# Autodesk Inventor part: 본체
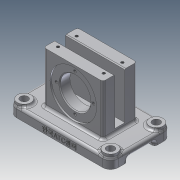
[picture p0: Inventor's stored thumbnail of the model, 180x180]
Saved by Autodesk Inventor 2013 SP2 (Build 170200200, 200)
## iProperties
Created: 2025-04
Part Number: 본체
Material: 알루미늄 6061
Document SubType Name: Modeling
Designer: i
Density: 2.71 g/cm^3
Mass: 495.705 g
Surface Area: 439.516 cm^2
Volume: 182.917 cm^3
Author: i
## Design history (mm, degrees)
sketch "스케치1"
  geometry: L1 (-35, 20)-(35, 20); L2 (35, 20)-(35, -20); L3 (35, -20)-(-35, -20); L4 (-35, -20)-(-35, 20); L5 (-35, 20)-(35, -20); L6 (35, 20)-(-35, -20); 1 further point
  constraints: 12 end point, 2 midpoint, 2 parallel, 1 horizontal, 1 perpendicular
  dimensions: "d0" = 70 distance of L2.end L3.end; "d2" = 40 distance of L3.end L1.start
extrude "돌출1" new body sketch "스케치1" distance "d3" = 72; taper "d4" = 0 deg
sketch "스케치2"
  geometry: L1 (35, 20)-(-35, 20) reference; L2 (-35, 20)-(-35, -20) reference; L3 (-35, -20)-(35, -20) reference; L4 (35, -20)-(35, 20) reference; L5 (-60, 36)-(60, 36); L6 (60, 36)-(60, -36); L7 (60, -36)-(-60, -36); L8 (-60, -36)-(-60, 36); L9 (-60, 36)-(60, -36); L10 (60, 36)-(-60, -36); 1 further point
  constraints: 12 end point, 2 midpoint, 2 parallel, 1 horizontal, 1 perpendicular
  dimensions: "d5" = 120 distance of L6.end L7.end; "d7" = 72 distance of L7.end L5.start
extrude "돌출2" join sketch "스케치2" distance "d8" = 12; taper "d9" = 0 deg
fillet "모깎기1" dims "d10" = 9
sketch "스케치3"
  geometry: C1 r 8 at (51, -27); A1 r 9 centre (51, -27) between (51, -36) and (60, -27) reference; 1 further point
  constraints: 1 centre point, 1 coincident
  dimensions: "d11" = 16 diameter of C1
extrude "돌출3" join sketch "스케치3" distance "d12" = 3; taper "d13" = 0 deg
sketch "스케치4"
  geometry: C1 r 8 at (0, 0) reference; C2 r 4.5 at (0, 0); 1 further point
  constraints: 1 centre point, 1 coincident
  dimensions: "d14" = 9 diameter of C2
extrude "돌출4" cut sketch "스케치4" stored distance "d15" = 3; taper "d16" = 0 deg
sketch "스케치5"
  geometry: L1 (0, 0)-(54, 0) reference; L2 (11, 5)-(43, 5); L3 (43, 5)-(43, 0); L4 (43, 0)-(11, 0); L5 (11, 0)-(11, 5); 2 further points
  constraints: 8 end point, 2 midpoint, 2 parallel, 1 horizontal, 1 perpendicular
  dimensions: "d17" = 32 distance of L2.start L2.end; "d19" = 5 distance of L2.end L3.end
extrude "돌출5" cut sketch "스케치5" stored distance "d20" = 3; taper "d21" = 0 deg
sketch "스케치6"
  geometry: L1 (70, 0)-(0, 0) reference; L2 (-16, -72)-(86, -72) reference; C1 r 17 at (35, -30); 2 further points
  constraints: 1 centre point, 1 midpoint, 1 vertical alignment
  dimensions: "d22" = 34 diameter of C1; "d23" = 42 distance from line of L2 C1.centre
extrude "돌출6" join sketch "스케치6" distance "d24" = 7; taper "d25" = 0 deg
sketch "스케치7"
  geometry: C1 r 17 at (0, 0) reference; C2 r 11 at (0, 0); 1 further point
  constraints: 1 centre point, 1 coincident
  dimensions: "d26" = 22 diameter of C2
extrude "돌출7" cut sketch "스케치7" stored distance "d27" = 7; taper "d28" = 0 deg
sketch "스케치8"
  geometry: L1 (40, 0)-(0, 0) reference; L2 (14, 0)-(26, 0); L3 (26, 0)-(26, -55); L4 (26, -55)-(14, -55); L5 (14, -55)-(14, 0); 2 further points
  constraints: 8 end point, 2 midpoint, 2 parallel, 1 horizontal, 1 perpendicular
  dimensions: "d29" = 12 distance of L3.end L4.end; "d31" = 55 distance of L2.end L3.end
extrude "돌출8" cut sketch "스케치8" stored distance "d32" = 7; taper "d33" = 0 deg
sketch "스케치9"
  geometry: C1 r 11 at (35, 25) reference; C2 r 15 at (35, 25); 1 further point
  constraints: 1 centre point, 1 coincident
  dimensions: "d34" = 30 diameter of C2
extrude "돌출9" cut sketch "스케치9" distance "d35" = 5; taper "d36" = 0 deg
sketch "스케치10"
  geometry: C1 r 11 at (35, -30) reference; C2 r 27.5 at (35, -30); 1 further point
  constraints: 1 centre point, 1 coincident
  dimensions: "d37" = 55 diameter of C2
extrude "돌출10" cut sketch "스케치10" distance "d38" = 2; taper "d39" = 0 deg
sketch "스케치11"
  geometry: C1 r 11 at (0, 0) reference; C2 r 27.5 at (0, 0) reference; C3 r 18 at (0, 0); 1 further point
  constraints: 1 centre point, 1 coincident
  dimensions: "d40" = 36 diameter of C3
extrude "돌출11" cut sketch "스케치11" stored distance "d41" = 2; taper "d42" = 0 deg
sketch "스케치12" dims "d43" = 44
  geometry: C1 r 27.5 at (0, 0) reference; 3 further points
  constraints: 2 vertical alignment, 1 coincident, 2 other
hole "구멍1" sketch "스케치12" at (0, 22) diameter "d44" = 3.242; stored, may be unused: countersink angle "d48" = 90 deg, drill point angle "d50" = 118 deg; dims "d45" = 8, "d46" = 4, "d47" = 2, "d49" = 10
sketch "스케치13"
  geometry: 5 further points
  constraints: 2 horizontal alignment, 2 vertical alignment
  dimensions: "d54" = 54 distance of point (27, 11) point (-27, 11); "d56" = 27 horizontal distance of point (0, 0) point (-27, 11); "d57" = 22 distance of point (-27, -11) point (-27, 11); "d58" = 11 vertical distance of point (0, 0) point (-27, -11)
hole "구멍2" sketch "스케치13" at (-27, 11), (27, 11), (27, -11), (-27, -11) diameter "d59" = 3.242; stored, may be unused: countersink angle "d63" = 90 deg, drill point angle "d65" = 118 deg; dims "d60" = 8, "d61" = 4, "d62" = 2, "d64" = 10
node "작업 평면1"
sketch "스케치14"
  geometry: L1 (111, 0)-(102, 0) reference; 2 further points
  constraints: 1 vertical alignment, 1 other
  dimensions: "d67" = 5 distance from line of L1 point (51, 5)
feature "엠보싱1" sketch "스케치14" dims "d0" = 70, "d2" = 40, "d68" = 0.5, "d69" = 0
fillet "모깎기2" dims "d70" = 3
fillet "모깎기3" dims "d71" = 3
fillet "모깎기5" dims "d73" = 3
fillet "모깎기6" dims "d74" = 3
fillet "모깎기7" dims "d75" = 3
fillet "모깎기8" dims "d76" = 3
fillet "모깎기9" dims "d77" = 3
chamfer "모따기1" distance "d78" = 1; stored, may be unused: second distance "d79" = 2, angle "d80" = 45 deg
chamfer "모따기2" distance "d81" = 1; stored, may be unused: second distance "d82" = 2, angle "d83" = 45 deg
chamfer "모따기3" distance "d84" = 1; stored, may be unused: second distance "d85" = 2, angle "d86" = 45 deg
node "솔리드1"
mirror "대칭1"
mirror "대칭2"
pattern_circular "원형 패턴1" dims angle "d52" = 360 deg
other parameters: "d66" = 13
